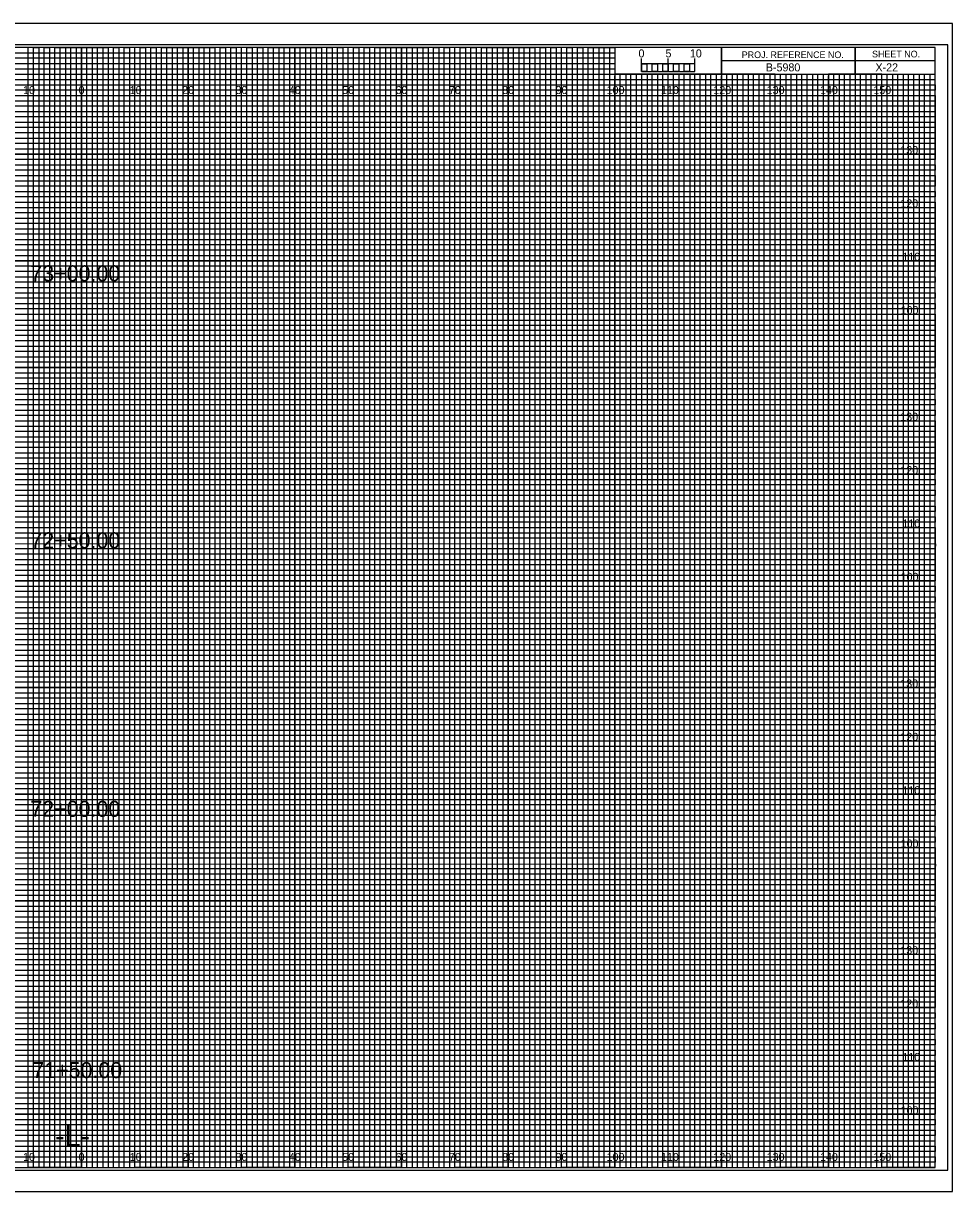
# Model space of a CAD drawing. Extents: x -13 to 323, y -5 to 1754.
# Drawn here: x 149.1 to 323.3, y 1315.5 to 1534.5 of the extents above; entities that cross this region are included whole.
import ezdxf

# ---------------------------------------------------------------- set-up
doc = ezdxf.new("R2010")
doc.units = 0
for name, color, linetype in [('Exist Cross Section Cell', 7, 'Continuous'), ('Exist XS Center Line Elevation Label', 7, 'Continuous'), ('Exist XS Ground Line', 7, 'Continuous'), ('Prop CMT Bridge Metal Rail', 7, 'Continuous'), ('Prop CMT Pvmt Course 1', 7, 'Continuous'), ('Prop CMT Pvmt Course 2', 7, 'Continuous'), ('Prop CMT Pvmt Course 3', 7, 'Continuous'), ('Prop CMT Pvmt Surface', 7, 'Continuous'), ('Prop CMT Pvmt Surface Shoulder', 7, 'Continuous'), ('Prop CMT Shld Paved Course 1', 7, 'Continuous'), ('Prop CMT Shld Paved Course 2', 7, 'Continuous'), ('Prop CMT Shld Paved Course 3', 7, 'Continuous'), ('Prop CMT Slope Grass', 7, 'Continuous'), ('Prop CMT Subgrade Earthwork', 7, 'Continuous'), ('Prop XS Shear Point Element', 7, 'Continuous'), ('Prop XS Shear Point Label', 7, 'Continuous'), ('Scratch_Level_1', 7, 'Continuous')]:
    doc.layers.add(name, color=color, linetype=linetype)

msp = doc.modelspace()

# ---------------------------------------------------------------- linework, layer by layer
at = {"layer": 'Exist XS Center Line Elevation Label'}
for points in [[(145, 1320), (155, 1320), (155, 1530), (165, 1530), (165, 1320), (175, 1320), (175, 1530), (185, 1530), (185, 1320), (195, 1320), (195, 1530), (205, 1530), (205, 1320), (215, 1320), (215, 1530), (225, 1530), (225, 1320), (235, 1320), (235, 1530), (245, 1530), (245, 1320), (255, 1320), (255, 1530), (259.93, 1530), (260, 1530), (260, 1525), (264.99, 1525), (264.99, 1320), (275, 1320), (275, 1525), (285, 1525), (285, 1320), (295, 1320), (295, 1525), (305, 1525), (305, 1320), (315, 1320), (315, 1525)], [(0, 1525), (275, 1525)], [(0, 1505), (320, 1505), (320, 1515), (0, 1515)], [(0, 1485), (320, 1485), (320, 1495), (0, 1495)], [(0, 1465), (320, 1465), (320, 1475), (0, 1475)], [(0, 1445), (320, 1445), (320, 1455), (0, 1455)], [(0, 1425), (320, 1425), (320, 1435), (0, 1435)], [(0, 1405), (320, 1405), (320, 1415), (0, 1415)], [(0, 1385), (320, 1385), (320, 1395), (0, 1395)], [(0, 1365), (320, 1365), (320, 1375), (0, 1375)], [(0, 1345), (320, 1345), (320, 1355), (0, 1355)], [(0, 1325), (320, 1325), (320, 1335), (0, 1335)]]:
    msp.add_lwpolyline(points, dxfattribs=at)
at = {"layer": 'Exist XS Ground Line'}
for p, q in [((150, 1530), (140, 1530)), ((150, 1320), (150, 1530)), ((170, 1530), (160, 1530)), ((160, 1530), (160, 1320)), ((170, 1320), (170, 1530)), ((190, 1530), (180, 1530)), ((180, 1530), (180, 1320)), ((190, 1320), (190, 1530)), ((210, 1530), (200, 1530)), ((200, 1530), (200, 1320)), ((210, 1320), (210, 1530)), ((230, 1530), (220, 1530)), ((220, 1530), (220, 1320)), ((230, 1320), (230, 1530)), ((250, 1530), (240, 1530)), ((240, 1530), (240, 1320)), ((250, 1320), (250, 1530)), ((260, 1530), (260, 1320)), ((270, 1320), (270, 1525)), ((290, 1525), (280, 1525)), ((280, 1525), (280, 1320)), ((290, 1320), (290, 1525)), ((310, 1525), (300, 1525)), ((300, 1525), (300, 1320)), ((310, 1320), (310, 1525)), ((160, 1320), (150, 1320)), ((180, 1320), (170, 1320)), ((200, 1320), (190, 1320)), ((220, 1320), (210, 1320)), ((240, 1320), (230, 1320)), ((260, 1320), (250, 1320)), ((280, 1320), (270, 1320)), ((300, 1320), (290, 1320)), ((320, 1320), (310, 1320)), ((320, 1320), (320, 1320))]:
    msp.add_line(p, q, dxfattribs=at)
for points in [[(0, 1520), (320, 1520), (320, 1510), (0, 1510)], [(0, 1500), (320, 1500), (320, 1490), (0, 1490)], [(0, 1480), (320, 1480), (320, 1470), (0, 1470)], [(0, 1460), (320, 1460), (320, 1450), (0, 1450)], [(0, 1440), (320, 1440), (320, 1430), (0, 1430)], [(0, 1420), (320, 1420), (320, 1410), (0, 1410)], [(0, 1400), (320, 1400), (320, 1390), (0, 1390)], [(0, 1380), (320, 1380), (320, 1370), (0, 1370)], [(0, 1360), (320, 1360), (320, 1350), (0, 1350)], [(0, 1340), (320, 1340), (320, 1330), (0, 1330)]]:
    msp.add_lwpolyline(points, dxfattribs=at)
at = {"layer": 'Prop CMT Pvmt Course 2'}
for p, q in [((265, 1525.49), (265, 1527.9)), ((265, 1526.9), (265, 1527.9)), ((270, 1525.49), (270, 1527.9)), ((275, 1525.49), (275, 1527.9)), ((275, 1526.9), (275, 1527.9))]:
    msp.add_line(p, q, dxfattribs=at)
for points in [[(275, 1526.9), (265, 1526.9), (265, 1525.49), (275, 1525.49)], [(265, 1526.9), (266, 1526.9), (266, 1525.49), (265, 1525.49)], [(267, 1526.9), (268, 1526.9), (268, 1525.49), (267, 1525.49)], [(269, 1526.9), (270, 1526.9), (270, 1525.49), (269, 1525.49)], [(271, 1526.9), (272, 1526.9), (272, 1525.49), (271, 1525.49)], [(273, 1526.9), (274, 1526.9), (274, 1525.49), (273, 1525.49)]]:
    msp.add_lwpolyline(points, close=True, dxfattribs=at)
at = {"layer": 'Prop CMT Pvmt Course 3'}
msp.add_lwpolyline([(-13.4, 1315.5), (323.3, 1315.5), (323.3, 1534.5), (-13.4, 1534.5)], close=True, dxfattribs=at)
at = {"layer": 'Prop CMT Pvmt Surface'}
for p, q in [((150, 1320), (150, 1530)), ((160, 1320), (160, 1530)), ((170, 1320), (170, 1530)), ((180, 1320), (180, 1530)), ((190, 1320), (190, 1530)), ((200, 1320), (200, 1530)), ((210, 1320), (210, 1530)), ((220, 1320), (220, 1530)), ((230, 1320), (230, 1530)), ((240, 1320), (240, 1530)), ((250, 1320), (250, 1530)), ((260, 1320), (260, 1524.69)), ((270, 1320), (270, 1524.69)), ((280, 1320), (280, 1524.69)), ((290, 1320), (290, 1524.69)), ((300, 1320), (300, 1524.69)), ((310, 1320), (310, 1524.69)), ((0, 1520), (320, 1520)), ((0, 1510), (320, 1510)), ((0, 1500), (320, 1500)), ((0, 1490), (320, 1490)), ((0, 1480), (320, 1480)), ((0, 1470), (320, 1470)), ((0, 1460), (320, 1460)), ((0, 1450), (320, 1450)), ((0, 1440), (320, 1440)), ((0, 1430), (320, 1430)), ((0, 1420), (320, 1420)), ((0, 1410), (320, 1410)), ((0, 1400), (320, 1400)), ((0, 1390), (320, 1390)), ((0, 1380), (320, 1380)), ((0, 1370), (320, 1370)), ((0, 1360), (320, 1360)), ((0, 1350), (320, 1350)), ((0, 1340), (320, 1340)), ((0, 1330), (320, 1330))]:
    msp.add_line(p, q, dxfattribs=at)
at = {"layer": 'Prop CMT Pvmt Surface Shoulder'}
for p, q in [((323.3, 1534.5), (-13.4, 1534.5)), ((-13.4, 1315.5), (323.3, 1315.5))]:
    msp.add_line(p, q, dxfattribs=at)
at = {"layer": 'Prop CMT Shld Paved Course 1'}
for p, q in [((0, 1529), (260, 1529)), ((260, 1529), (260, 1527.98)), ((260, 1527.98), (0, 1527.98)), ((0, 1527), (260, 1527)), ((260, 1527), (260, 1525.89)), ((260, 1525.89), (0, 1525.89)), ((0, 1524), (320, 1524))]:
    msp.add_line(p, q, dxfattribs=at)
for points in [[(0, 1523), (270, 1523), (320, 1523), (320, 1522), (0, 1522)], [(0, 1521), (320, 1521), (320, 1519), (0, 1519)], [(0, 1518), (320, 1518), (320, 1517), (0, 1516.98)], [(0, 1516), (320, 1516), (320, 1514), (0, 1514)], [(0, 1513), (320, 1513), (320, 1512), (0, 1512)], [(0, 1511), (320, 1511), (320, 1509), (0, 1509)], [(0, 1508), (320, 1508), (320, 1507), (0, 1507)], [(0, 1506), (320, 1506), (320, 1504), (0, 1504)], [(0, 1503), (320, 1503), (320, 1502), (0, 1502)], [(0, 1501), (320, 1501), (320, 1499), (0, 1499)], [(0, 1498), (320, 1498), (320, 1497), (0, 1497)], [(0, 1496), (320, 1496), (320, 1493.95), (320, 1493), (320, 1492), (0, 1492)], [(0, 1494), (320, 1494), (320, 1493), (0, 1493)], [(0, 1491), (320, 1491), (320, 1489), (0, 1489.03)], [(0, 1489.03), (320, 1489), (320, 1488), (0, 1488)], [(0, 1487), (320, 1487), (320, 1486), (0, 1486)], [(0, 1484), (320, 1484), (320, 1483), (0, 1483)], [(0, 1482), (320, 1482), (320, 1481), (0, 1481)], [(-0.07, 1478.89), (320, 1478.89), (320, 1477.88), (-0.07, 1477.88)], [(0, 1477), (320, 1477), (320, 1476), (0, 1476)], [(0, 1474), (320, 1474), (320, 1473), (0, 1473)], [(0, 1472), (320, 1472), (320, 1471), (0, 1471)], [(0, 1469), (320, 1469), (320, 1468), (0, 1468)], [(0, 1467), (320, 1467), (320, 1466), (0, 1466)], [(0, 1464), (320, 1464), (320, 1463), (0, 1463)], [(0, 1462), (320, 1462), (320, 1461), (0, 1461)], [(0, 1459), (320, 1459), (319.99, 1457.98), (0, 1458)], [(0, 1457), (320, 1457), (320, 1456), (0, 1456)], [(0, 1454), (320, 1454), (320, 1453), (0, 1453)], [(0, 1452), (320, 1452), (320, 1451), (0, 1451)], [(0, 1449), (320, 1449), (320, 1448), (0, 1448)], [(0, 1447), (320, 1447), (320, 1446), (0, 1446)], [(0, 1444), (320, 1444), (320, 1443), (0, 1443)], [(0, 1442), (320, 1442), (320, 1441), (0, 1441)], [(0, 1439), (320, 1439), (320, 1438), (0, 1438)], [(0, 1436.99), (320.07, 1436.91), (320, 1436), (0, 1436)], [(0, 1434), (320, 1434), (320, 1433), (0, 1433)], [(0, 1432), (320, 1432), (320, 1431), (0, 1431)], [(0, 1429), (320, 1429), (320, 1428), (0, 1428)], [(0, 1427), (320, 1427), (320, 1426), (0, 1426)], [(0, 1424), (320, 1424), (320, 1423), (0, 1423)], [(0, 1422), (320, 1422), (320, 1421), (0, 1421)], [(0, 1419), (320, 1419), (320, 1418), (0, 1418)], [(0, 1417), (320, 1417), (320, 1416), (0, 1416)], [(0, 1414), (320, 1414), (320, 1413), (0, 1413)], [(0, 1412), (320, 1412), (320, 1411), (0, 1411)], [(0, 1409), (320, 1409), (320, 1408), (0, 1408)], [(0, 1407), (320, 1407), (320, 1406), (0, 1406)], [(0, 1404), (320, 1404), (320, 1403), (0, 1403)], [(0, 1402), (320, 1402), (320, 1401), (0, 1401)], [(0, 1399), (320, 1399), (319.99, 1397.98), (0, 1398)], [(0, 1397), (320, 1397), (320, 1396), (0, 1396)], [(0, 1394), (320, 1394), (320, 1393), (0, 1393)], [(0, 1392), (320, 1392), (320, 1391), (0, 1391)], [(0, 1389), (320, 1389), (320, 1388), (0, 1388)], [(0, 1387), (320, 1387), (320, 1386), (0, 1386)], [(0, 1384), (320, 1384), (320, 1383), (0, 1383)], [(0, 1382), (320, 1382), (320, 1381), (0, 1381)], [(0, 1379), (320, 1379), (320, 1378), (0, 1378)], [(0, 1376.99), (320.07, 1376.91), (320, 1376), (0, 1376)], [(0, 1374), (320, 1374), (320, 1373), (0, 1373)], [(0, 1372), (320, 1372), (320, 1371), (0, 1371)], [(0, 1369), (320, 1369), (320, 1368), (0, 1368)], [(0, 1367), (320, 1367), (320, 1366), (0, 1366)], [(0, 1364), (320, 1364), (320, 1363), (0, 1363)], [(0, 1362), (320, 1362), (320, 1361), (0, 1361)], [(0, 1359), (320, 1359), (320, 1358), (0, 1358)], [(0, 1357), (320, 1357), (320, 1356), (0, 1356)], [(0, 1354), (320, 1354), (320, 1353), (0, 1353)], [(0, 1352), (320, 1352), (320, 1351), (0, 1351)], [(0, 1349), (320, 1349), (320, 1348), (0, 1348)], [(0, 1347), (320, 1347), (320, 1346), (0, 1346)], [(0, 1344), (320, 1344), (320, 1343), (0, 1343)], [(0, 1342), (320, 1342), (320, 1341), (0, 1341)], [(0, 1339), (320, 1339), (320, 1338), (0, 1338)], [(0, 1337), (320, 1337), (320, 1336), (0, 1336)], [(0, 1334), (320, 1334), (320, 1333), (0, 1333)], [(0, 1332), (320, 1332), (320, 1331), (0, 1331)], [(0, 1329), (320, 1329), (320, 1328), (0, 1328)], [(0, 1327), (320, 1327), (320, 1326), (0, 1326)], [(0, 1324), (320, 1324), (320, 1323), (0, 1323)], [(0, 1322), (320, 1322), (320, 1321), (0, 1321)]]:
    msp.add_lwpolyline(points, dxfattribs=at)
at = {"layer": 'Prop CMT Shld Paved Course 2'}
for p, q in [((305, 1530), (305, 1525)), ((305, 1525), (305, 1530)), ((280, 1527.5), (280, 1525)), ((320, 1527.49), (280, 1527.49)), ((280, 1525), (320, 1525))]:
    msp.add_line(p, q, dxfattribs=at)
for points in [[(320, 1530), (0, 1530), (0, 1320), (320, 1320)], [(280, 1530), (260, 1530), (260, 1525.03), (280, 1525.03)], [(320, 1530), (280, 1530), (280, 1525), (320, 1525)]]:
    msp.add_lwpolyline(points, close=True, dxfattribs=at)
at = {"layer": 'Prop CMT Shld Paved Course 3'}
for p, q in [((267, 1525), (266.01, 1525)), ((266.01, 1525), (266.01, 1320)), ((267, 1320), (267, 1525)), ((269, 1525), (268, 1525)), ((268, 1525), (268, 1320)), ((269, 1320), (269, 1525)), ((266.01, 1320), (265, 1320)), ((268, 1320), (267, 1320))]:
    msp.add_line(p, q, dxfattribs=at)
for points in [[(150, 1320), (151, 1320), (151, 1530), (152, 1530), (152, 1320)], [(152, 1320), (153, 1320), (153, 1530), (154, 1530), (154, 1320)], [(155, 1320), (156, 1320), (156, 1530), (157, 1530), (157, 1320)], [(157, 1320), (158, 1320), (158, 1530), (159, 1530), (159, 1320)], [(160, 1320), (161, 1320), (161, 1530), (162, 1530), (162, 1320)], [(162, 1320), (163, 1320), (163, 1530), (164, 1530), (164, 1320)], [(165, 1320), (166, 1320), (166, 1530), (167, 1530), (167, 1320)], [(167, 1320), (168, 1320), (168, 1530), (169, 1530), (169, 1320)], [(170, 1320), (171, 1320), (171, 1530), (172, 1530), (172, 1320)], [(172, 1320), (173, 1320), (173, 1530), (174, 1530), (174, 1320)], [(175, 1320), (176, 1320), (176, 1530), (177, 1530), (177, 1320)], [(177, 1320), (178, 1320), (178, 1530), (179, 1530), (179, 1320)], [(180, 1320), (181, 1320), (181, 1530), (182, 1530), (182, 1320)], [(182, 1320), (183, 1320), (183, 1530), (184, 1530), (184, 1320)], [(185, 1320), (186, 1320), (186, 1530), (187, 1530), (187, 1320)], [(187, 1320), (188, 1320), (188, 1530), (189, 1530), (189, 1320)], [(190, 1320), (191, 1320), (191, 1530), (192, 1530), (192, 1320)], [(192, 1320), (193, 1320), (193, 1530), (194, 1530), (194, 1320)], [(195, 1320), (196, 1320), (196, 1530), (197, 1530), (197, 1320)], [(197, 1320), (198, 1320), (198, 1530), (199, 1530), (199, 1320)], [(200, 1320), (201, 1320), (201, 1530), (202, 1530), (202, 1320)], [(202, 1320), (203, 1320), (203, 1530), (204, 1530), (204, 1320)], [(205, 1320), (206, 1320), (206, 1530), (207, 1530), (207, 1320)], [(207, 1320), (208, 1320), (208, 1530), (209, 1530), (209, 1320)], [(210, 1320), (211, 1320), (211, 1530), (212, 1530), (212, 1320)], [(212, 1320), (213, 1320), (213, 1530), (214, 1530), (214, 1320)], [(215, 1320), (216, 1320), (216, 1530), (217, 1530), (217, 1320)], [(217, 1320), (218, 1320), (218, 1530), (219, 1530), (219, 1320)], [(220, 1320), (221, 1320), (221, 1530), (222, 1530), (222, 1320)], [(222, 1320), (223, 1320), (223, 1530), (224, 1530), (224, 1320)], [(225, 1320), (226, 1320), (226, 1530), (227, 1530), (227, 1320)], [(227, 1320), (228, 1320), (228, 1530), (229, 1530), (229, 1320)], [(230, 1320), (231, 1320), (231, 1530), (232, 1530), (232, 1320)], [(232, 1320), (233, 1320), (233, 1530), (234, 1530), (234, 1320)], [(235, 1320), (236, 1320), (236, 1530), (237, 1530), (237, 1320)], [(237, 1320), (238, 1320), (238, 1530), (239, 1530), (239, 1320)], [(240, 1320), (241, 1320), (241, 1530), (242, 1530), (242, 1320)], [(242, 1320), (243, 1320), (243, 1530), (244, 1530), (244, 1320)], [(245, 1320), (246, 1320), (246, 1530), (247, 1530), (247, 1320)], [(247, 1320), (248, 1320), (248, 1530), (249, 1530), (249, 1320)], [(250, 1320), (251, 1320), (251, 1530), (252, 1530), (252, 1320)], [(252, 1320), (253, 1320), (253, 1530), (254, 1530), (254, 1320)], [(255, 1320), (256, 1320), (256, 1530), (257, 1530), (257, 1320)], [(257, 1320), (258, 1320), (258, 1530), (259, 1530), (259, 1320)], [(260, 1320), (261, 1320), (261, 1525), (262.02, 1525), (262.02, 1320)], [(262, 1320), (263, 1320), (263, 1525), (263.99, 1525), (263.99, 1320)], [(270, 1320), (270.98, 1320), (270.98, 1525), (272, 1525), (272, 1320)], [(272, 1320), (273, 1320), (273, 1525), (274.05, 1525), (274.05, 1320)], [(275, 1320), (276, 1320), (276, 1525), (277, 1525), (277, 1320)], [(277, 1320), (278, 1320), (278, 1525), (279, 1525), (279, 1320)], [(280, 1320), (281, 1320), (281, 1525), (282, 1525), (282, 1320)], [(282, 1320), (283, 1320), (283, 1525), (284, 1525), (284, 1320)], [(285, 1320), (286, 1320), (286, 1525), (287, 1525), (287, 1320)], [(287, 1320), (288, 1320), (288, 1525), (289, 1525), (289, 1320)], [(290, 1320), (291, 1320), (291, 1525), (292, 1525), (292, 1320)], [(292, 1320), (293, 1320), (293, 1525), (294, 1525), (294, 1320)], [(295, 1320), (296, 1320), (296, 1525), (297, 1525), (297, 1320)], [(297, 1320), (298, 1320), (298, 1525), (299, 1525), (299, 1320)], [(300, 1320), (301, 1320), (301, 1525), (302, 1525), (302, 1320)], [(302, 1320), (303, 1320), (303, 1525), (304, 1525), (304, 1320)], [(305, 1320), (306, 1320), (306, 1525), (307, 1525), (307, 1320)], [(307, 1320), (308, 1320), (308, 1525), (309, 1525), (309, 1320)], [(310, 1320), (311, 1320), (311, 1525), (312, 1525), (312, 1320)], [(312, 1320), (313, 1320), (313, 1525), (314, 1525), (314, 1320)], [(315, 1320), (316, 1320), (316, 1525), (317, 1525), (317, 1320)], [(317, 1320), (318, 1320), (318, 1525), (319, 1525), (319, 1320)]]:
    msp.add_lwpolyline(points, dxfattribs=at)
at = {"layer": 'Prop CMT Subgrade Earthwork'}
msp.add_lwpolyline([(-10.8, 1319.5), (322.4, 1319.5), (322.4, 1530.5), (-10.8, 1530.5)], close=True, dxfattribs=at)

# ---------------------------------------------------------------- texts
at = {"layer": 'Exist Cross Section Cell'}
for s, p in [('10', (149.04, 1521.25)), ('0', (159.45, 1521.25)), ('0', (159.45, 1521.25)), ('10', (169.04, 1521.25)), ('20', (178.86, 1521.25)), ('30', (188.86, 1521.25)), ('40', (198.86, 1521.25)), ('50', (208.86, 1521.25)), ('60', (218.86, 1521.25)), ('70', (228.86, 1521.25)), ('80', (238.86, 1521.25)), ('90', (248.86, 1521.25)), ('100', (258.44, 1521.25)), ('110', (268.62, 1521.25)), ('120', (278.44, 1521.25)), ('130', (288.44, 1521.25)), ('140', (298.44, 1521.25)), ('150', (308.44, 1521.25)), ('10', (149.04, 1321.25)), ('0', (159.45, 1321.25)), ('0', (159.45, 1321.25)), ('10', (169.04, 1321.25)), ('20', (178.86, 1321.25)), ('30', (188.86, 1321.25)), ('40', (198.86, 1321.25)), ('50', (208.86, 1321.25)), ('60', (218.86, 1321.25)), ('70', (228.86, 1321.25)), ('80', (238.86, 1321.25)), ('90', (248.86, 1321.25)), ('100', (258.44, 1321.25)), ('110', (268.62, 1321.25)), ('120', (278.44, 1321.25)), ('130', (288.44, 1321.25)), ('140', (298.44, 1321.25)), ('150', (308.44, 1321.25))]:
    msp.add_text(s, height=1.5, dxfattribs=at).set_placement(p)
at = {"layer": 'Prop CMT Bridge Metal Rail'}
for s, p in [('5', (269.47, 1528.12)), ('10', (274.04, 1528.12))]:
    msp.add_text(s, height=1.5, dxfattribs=at).set_placement(p)
at = {"layer": 'Prop CMT Pvmt Course 1'}
for s, p in [('130', (313.49, 1510)), ('120', (313.5, 1500)), ('110', (313.88, 1490)), ('100', (313.55, 1480)), ('130', (313.49, 1460)), ('120', (313.5, 1450)), ('110', (313.88, 1440)), ('100', (313.55, 1430)), ('130', (313.49, 1410)), ('120', (313.5, 1400)), ('110', (313.88, 1390)), ('100', (313.55, 1380)), ('130', (313.49, 1360)), ('120', (313.5, 1350)), ('110', (313.88, 1340)), ('100', (313.55, 1330))]:
    msp.add_text(s, height=1.5, dxfattribs=at).set_placement(p)
at = {"layer": 'Prop CMT Pvmt Course 2'}
msp.add_text('0', height=1.5, dxfattribs=at).set_placement((264.41, 1528.12))
at = {"layer": 'Prop CMT Shld Paved Course 2'}
for s, p in [('PROJ. REFERENCE NO.', (283.77, 1527.99)), ('SHEET NO.', (308.19, 1528.12))]:
    msp.add_text(s, height=1.25, dxfattribs=at).set_placement(p)
at = {"layer": 'Prop CMT Slope Grass'}
for s, p in [('73+00.00', (150.41, 1486.14)), ('72+50.00', (150.41, 1436.09)), ('72+00.00', (150.41, 1385.76)), ('71+50.00', (150.77, 1336.78))]:
    msp.add_text(s, height=3, dxfattribs=at).set_placement(p)
at = {"layer": 'Prop XS Shear Point Element'}
msp.add_text('-L-', height=4, dxfattribs=at).set_placement((155.06, 1324))
at = {"layer": 'Prop XS Shear Point Label'}
msp.add_text('B-5980', height=1.5, dxfattribs=at).set_placement((288.28, 1525.5))
at = {"layer": 'Scratch_Level_1'}
msp.add_text('X-22', height=1.5, dxfattribs=at).set_placement((308.83, 1525.5))

doc.saveas('drawing.dxf')
